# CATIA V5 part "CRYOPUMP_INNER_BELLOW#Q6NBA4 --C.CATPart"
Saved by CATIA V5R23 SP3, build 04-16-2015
Part number: CRYOPUMP_INNER_BELLOW#Q6NB9P
Revision: --C
Nomenclature: _
Description: CRYOPUMP_INNER_BELLOW
Property "MAT": "PR"
Property "Long Description": "BELLOWS_PORT_PUMP_CONNECTION_C+GS"
Property "PBS Short": "3.1"
Property "VAC & FUEL CLASS": "N"
Property "GAS CLASS": "N"
Property "WATER CLASS": "N"
Property "ELEC CLASS": "N"
Property "CODAC CLASS": "N"
Property "RH CLASS": "N"
Property "HEAT CLASS": "N"
Property "DIAG CLASS": "N"
Property "CRYO CLASS": "N"
Property "NEU CLASS": "N"
Property "ASSY CLASS": "N"
Property "SAFETY CLASS": "N"
Property "QA CLASS": "N"
Property "DEPT": "_"
Property "DIVN": "_"
Property "GROUP": "_"
Property "UNIT": "_"
Property "PARTY": "_"
Property "RO": "IOKIK"
Property "RE": "SEKACHI"
Property "PRO": "---"
Property "Part Code": "TXT1"
Property "Part Origin": "--"
Property "ITER Part Version": "--"
Property "PBS Full Meaning": "VACUUM PUMPING"
Property "Date": "2005-11-14-11.11.21.000000"
Property "Responsible": "GLISSC"
Property "Site Resp": "SITE_AA"
Property "Organization": "ITER"
Property "Former PN": "ITER-P-32JR6F"
Property "CHK MAT": "SLAVE"
Property "PBS": "3.1 VACUUM PUMPING"
Property "Sig. Point Calc.": "N"
Property "ShortDescMig": "CRYOP_BELLOW_CONNECT"
Property "PbsLevel1Mig": "31"
Property "PNMig": "235PQA"
Property "User In Enovia": "VAUQUEJ"
Property "Life Cycle Status": "Approved"
Property "ID": "Q6NB9P"
Property "AT": "PD"
Property "PBS 1": "24"
Property "PBS 2": "CR"
Property "PBS 3": "LC"
Property "LONG": "-"
Property "PREF": "Y"
Property "Change Type": "Major"
Property "Maturity Level": "CD"
Property "Export Number": "_"
Property "REP": "CM"
Property "Object Type": "_"
Property "CADENAS_ID": "_"
Property "Description Modification": "FDR Model"
Property "Description Documents": "_"
Property "BOM": "_"
Property "External Part ID": "ITER-C-235PPT"
Material "X2CrNiMoN17-11-2 1.4406 (316L(N))": density 7950 kg/m3, Young's modulus 2e+11 Pa, Poisson ratio 0.3, thermal expansion 1.6e-05 1/K
Bounding box of the stored display mesh (mm): x 13060 to 13980, y -639.95 to 639.95, z -5032.445 to -3753.555
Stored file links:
  C:\Users\pandeym\Desktop\__TCPH\CRYOPUMP_INNER_BELLOW#Q6NBA4 --C.CATPart
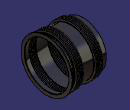
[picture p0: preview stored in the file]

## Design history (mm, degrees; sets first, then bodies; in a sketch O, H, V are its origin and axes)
Set1
  Line1 "CRYOPUMP_CENTER_AXIS": linked copy from another document
  Sketch1 "INNER_BELLOWS_RIGID_CYLINDER", origin (0, 0, 0), H (-1, 0, 0), V (0, 0, 1), geometry linked from another document
  Sketch2 "CRYOPUMP_INNER_BELLOWS", origin (0, 0, 0), H (-1, 0, 0), V (0, 0, 1), geometry linked from another document
  Sketch3 "CRYOPUMP_BACK_FLANGE", origin (0, 0, 0), H (-1, 0, 0), V (0, 0, 1), geometry linked from another document
  Sketch4 "CRYOPUMP_BELLOWS_BACK_FLANGE_CYLINDERS", origin (0, 0, 0), H (-1, 0, 0), V (0, 0, 1), geometry linked from another document
  Sketch5 "CRYOPUMP_FRONT_FLANGE", origin (0, 0, 0), H (1, 0, 0), V (0, 0, 1), geometry linked from another document
Body1 "INTERNAL" (main body)
  Shaft1: profile Sketch2, axis Line1, angle 180, second angle 180, thin wall 0.75, second thickness 0.75
Body2
  Shaft2: profile Sketch1, axis axis of face of Shaft1, angle 180, second angle 180
Body3
  Sketch6 on zx-plane, origin (0, 0, 0), H (-1, 0, 0), V (0, 0, 1)
    projected line E1 (-13980, -3753) -> (-13980, -3833) from edge of Sketch3
    projected line E2 (-13960, -3833) -> (-13960, -3753) from edge of Sketch3
    projected line E3 (-13960, -3818) -> (-13960, -3753) from edge of Sketch3
    projected line E4 (-13860, -3818) -> (-13960, -3818) from edge of Sketch4
    projected line E5 (-13860, -3833) -> (-13860, -3818) from edge of Sketch4
    projected line E6 (-13980, -3833) -> (-13960, -3833) from edge of Sketch3
    projected line E7 (-13960, -3833) -> (-13860, -3833) from edge of Sketch4
    projected line E8 (-13190, -3833) -> (-13190, -3818) from edge of Sketch5
    projected line E9 (-13190, -3818) -> (-13060, -3818) from edge of Sketch5
    projected line E10 (-13060, -3818) -> (-13060, -3833) from edge of Sketch5
    projected line E11 (-13060, -3833) -> (-13190, -3833) from edge of Sketch5
    projected line E12 (-13980, -3753) -> (-13960, -3753) from edge of Sketch3
  Shaft3: profile Sketch6, axis axis of face of Shaft2, angle 180, second angle 180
